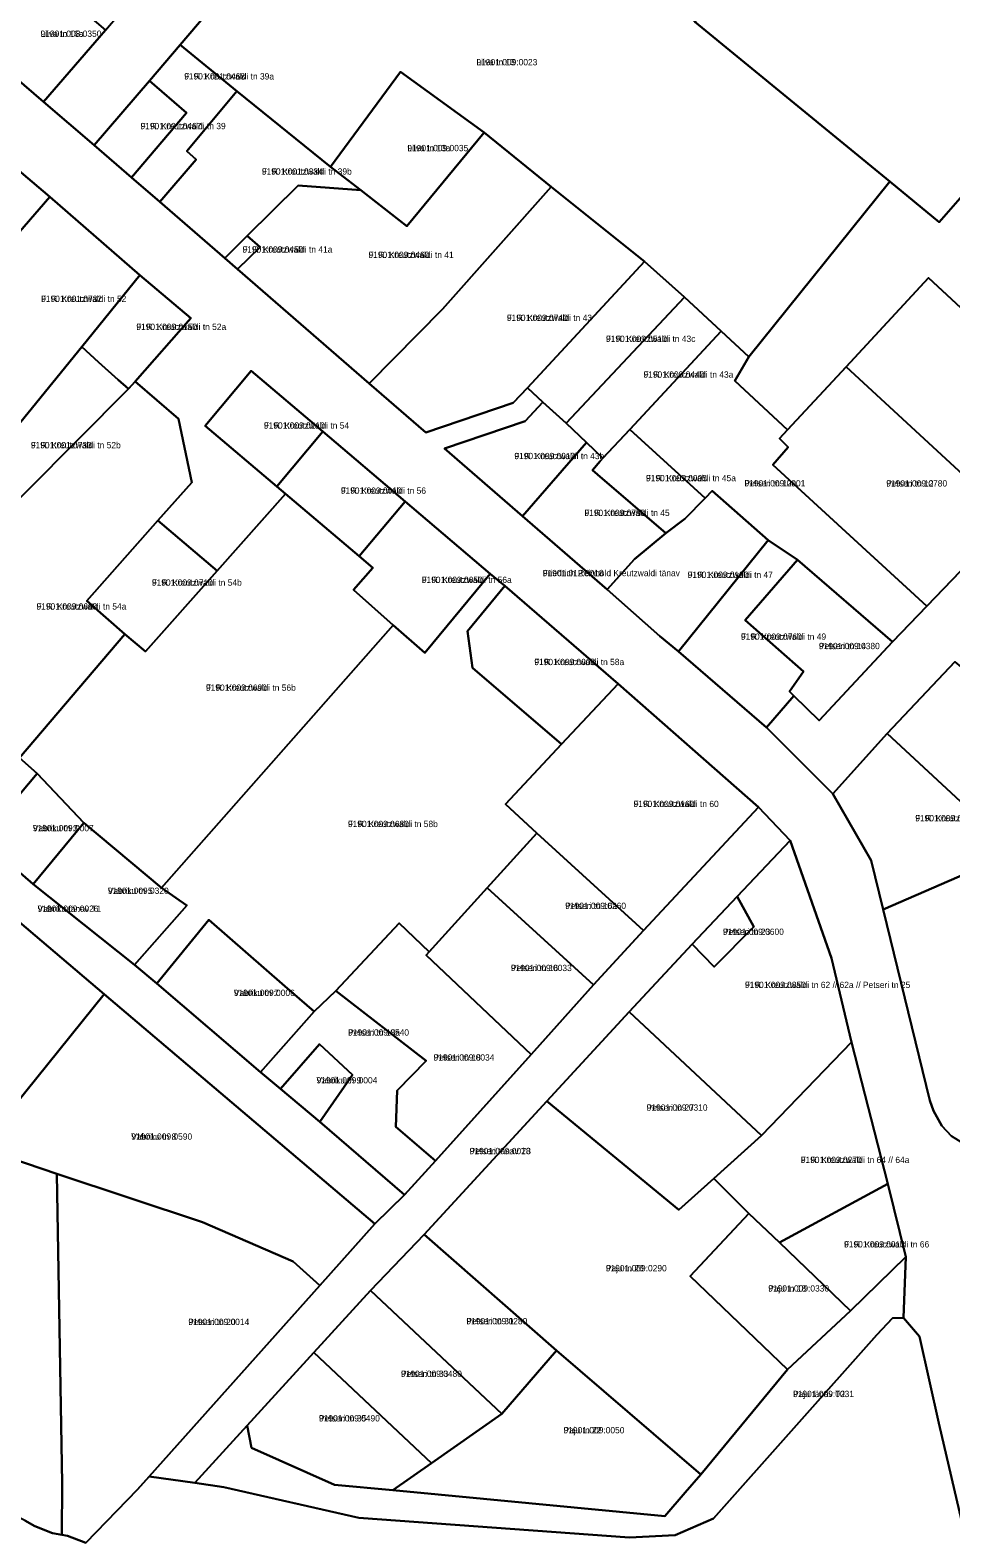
# Model space of a CAD drawing. Extents: x 675810 to 681273, y 6411190 to 6417565.
# Drawn here: x 678044.7 to 678264, y 6414897.2 to 6415256.1 of the extents above; entities that cross this region are included whole.
import ezdxf

# ---------------------------------------------------------------- set-up
doc = ezdxf.new("R2010")
doc.units = 0
for name, color, linetype in [('L_AADRESS', 7, 'Continuous'), ('PIIR', 7, 'Continuous'), ('TUNNUS', 7, 'Continuous')]:
    doc.layers.add(name, color=color, linetype=linetype)

msp = doc.modelspace()

# ---------------------------------------------------------------- linework, layer by layer
at = {"layer": 'PIIR'}
for points in [[(678198.81, 6415413.28), (678208.34, 6415402.14), (678200.49, 6415393.13), (678164.36, 6415350.68), (678161.07, 6415346.92), (678138.62, 6415320.63), (678158.43, 6415303.7), (678172.98, 6415291.47), (678169.9, 6415287.94), (678135.46, 6415317.19), (678080.44, 6415252.61), (678073.13, 6415244.08), (678060, 6415228.7), (678047.94, 6415239.03), (678062.66, 6415256.13), (678076.36, 6415272.05), (678099.99, 6415298.95), (678104.07, 6415303.65), (678126.77, 6415330.16), (678145.87, 6415352.47), (678149.44, 6415356.72), (678166.7, 6415375.98)], [(678286, 6415295.42), (678307.89, 6415320.24), (678311.89, 6415316.79), (678281.19, 6415282.24), (678297.38, 6415268.09), (678305.48, 6415261.06), (678291.98, 6415245.77), (678267.33, 6415217.4), (678261.23, 6415210.39), (678249.44, 6415220.06), (678203, 6415258.09), (678225.15, 6415284.07), (678228.71, 6415288.25), (678248, 6415310.9), (678261.57, 6415299.25), (678269.93, 6415309.22), (678270.63, 6415310.04)], [(678135.46, 6415317.19), (678169.9, 6415287.94), (678179.14, 6415279.62), (678203, 6415258.09), (678249.44, 6415220.06), (678215.92, 6415178.31), (678209.26, 6415184.48), (678200.6, 6415192.59), (678191.04, 6415201.02), (678168.78, 6415218.8), (678152.86, 6415231.73), (678132.93, 6415246.21), (678116.26, 6415223.58), (678093.94, 6415241.63), (678080.44, 6415252.61)], [(678046.56, 6415269.92), (678062.66, 6415256.13), (678047.94, 6415239.03), (678031.73, 6415252.94)], [(678081.99, 6415236.4), (678073.13, 6415244.08), (678080.44, 6415252.61), (678093.94, 6415241.63), (678082.01, 6415227.29), (678084.27, 6415225.36), (678075.6, 6415215.22), (678068.87, 6415221.01)], [(678132.93, 6415246.21), (678152.86, 6415231.73), (678134.44, 6415209.42), (678123.44, 6415218.03), (678116.26, 6415223.58)], [(678068.87, 6415221.01), (678060, 6415228.7), (678073.13, 6415244.08), (678081.99, 6415236.4)], [(678093.94, 6415241.63), (678116.26, 6415223.58), (678123.44, 6415218.03), (678108.53, 6415219.15), (678096.44, 6415207.12), (678091.12, 6415201.82), (678075.6, 6415215.22), (678084.27, 6415225.36), (678082.01, 6415227.29)], [(678094.14, 6415199.21), (678099.47, 6415204.49), (678096.44, 6415207.12), (678108.53, 6415219.15), (678123.44, 6415218.03), (678134.44, 6415209.42), (678152.86, 6415231.73), (678168.78, 6415218.8), (678142.93, 6415189.67), (678125.47, 6415172.03)], [(678037.29, 6415226.68), (678049.41, 6415216.4), (678023.87, 6415186.98), (677999.36, 6415158.83), (677982.03, 6415139.05), (677965.99, 6415120.49), (677959.89, 6415113.46), (677928.58, 6415077.34), (677882.86, 6415023.65), (677872.66, 6415034.51), (677904.65, 6415072.43), (677930.93, 6415102.56), (677951.46, 6415126.08), (677968.44, 6415145.74), (677980.8, 6415159.74), (678004.47, 6415187.8), (678013.63, 6415198.64)], [(678023.87, 6415186.98), (678049.41, 6415216.4), (678070.82, 6415197.78), (678057.06, 6415180.69), (678037.28, 6415156.5), (678030.6, 6415162.51), (678039.09, 6415173.99)], [(678142.93, 6415189.67), (678168.78, 6415218.8), (678191.04, 6415201.02), (678163.14, 6415170.98), (678159.79, 6415167.37), (678138.99, 6415160.32), (678125.47, 6415172.03)], [(678091.12, 6415201.82), (678096.44, 6415207.12), (678099.47, 6415204.49), (678094.14, 6415199.21)], [(678200.6, 6415192.59), (678172.35, 6415162.53), (678166.81, 6415167.58), (678163.14, 6415170.98), (678191.04, 6415201.02)], [(678082.96, 6415187.53), (678069.76, 6415172.45), (678068.17, 6415170.73), (678065.72, 6415172.89), (678061.01, 6415177.11), (678057.06, 6415180.69), (678070.82, 6415197.78)], [(678239.06, 6415175.98), (678258.66, 6415197.14), (678298.17, 6415160.58), (678278.26, 6415139.8)], [(678209.26, 6415184.48), (678187.54, 6415161.07), (678181.12, 6415154.2), (678177.19, 6415157.93), (678172.35, 6415162.53), (678200.6, 6415192.59)], [(678187.54, 6415161.07), (678209.26, 6415184.48), (678215.92, 6415178.31), (678212.58, 6415172.65), (678225.11, 6415161), (678223.16, 6415158.94), (678225.29, 6415156.87), (678221.64, 6415152.67), (678258.25, 6415118.98), (678250.12, 6415110.52), (678227.47, 6415130.05), (678220.53, 6415134.69), (678207.16, 6415146.42), (678205.48, 6415144.72)], [(678037.28, 6415156.5), (678057.06, 6415180.69), (678061.01, 6415177.11), (678065.72, 6415172.89), (678068.17, 6415170.73), (678031.79, 6415134.21), (678027.72, 6415137.35), (678021.6, 6415141.8), (678027.17, 6415148.45), (678022.82, 6415152.09), (678030.6, 6415162.51)], [(678097.33, 6415175.04), (678114.4, 6415160.6), (678103.51, 6415147.49), (678086.43, 6415161.9)], [(678225.11, 6415161), (678239.06, 6415175.98), (678278.26, 6415139.8), (678258.25, 6415118.98), (678221.64, 6415152.67), (678225.29, 6415156.87), (678223.16, 6415158.94)], [(678069.76, 6415172.45), (678080.05, 6415163.56), (678083.23, 6415148.47), (678075.16, 6415139.39), (678058.19, 6415120.25), (678067.3, 6415112.34), (678042.15, 6415082.88), (678029.02, 6415094.42), (678027.51, 6415095.75), (678015.11, 6415107.3), (678017.12, 6415109.61), (678009.23, 6415115.87), (678027.72, 6415137.35), (678031.79, 6415134.21), (678068.17, 6415170.73)], [(678166.81, 6415167.58), (678172.35, 6415162.53), (678177.19, 6415157.93), (678162.01, 6415140.39), (678143.38, 6415156.52), (678162.6, 6415163.04)], [(678134.02, 6415143.91), (678123.07, 6415130.89), (678105.57, 6415145.74), (678103.51, 6415147.49), (678114.4, 6415160.6)], [(678181.12, 6415154.2), (678187.54, 6415161.07), (678205.48, 6415144.72), (678200.62, 6415139.8), (678196.14, 6415136.39), (678179.84, 6415150.34), (678178.62, 6415151.38), (678180.48, 6415153.48)], [(678162.01, 6415140.39), (678177.19, 6415157.93), (678181.12, 6415154.2), (678180.48, 6415153.48), (678178.62, 6415151.38), (678179.84, 6415150.34), (678196.14, 6415136.39), (678188.64, 6415130.16), (678182.12, 6415122.99)], [(678131.21, 6415114.51), (678076.01, 6415051.96), (678057.54, 6415067.4), (678046.39, 6415079.16), (678042.15, 6415082.88), (678067.3, 6415112.34), (678072.16, 6415108.18), (678089.26, 6415127.4), (678105.57, 6415145.74), (678123.07, 6415130.89), (678126.3, 6415128.15), (678121.7, 6415122.92)], [(678191.23, 6415114.92), (678182.12, 6415122.99), (678188.64, 6415130.16), (678196.14, 6415136.39), (678200.62, 6415139.8), (678205.48, 6415144.72), (678207.16, 6415146.42), (678220.53, 6415134.69), (678199.12, 6415108.22), (678194.71, 6415111.83)], [(678123.07, 6415130.89), (678134.02, 6415143.91), (678154.29, 6415126.67), (678138.7, 6415107.87), (678131.21, 6415114.51), (678121.7, 6415122.92), (678126.3, 6415128.15)], [(678058.19, 6415120.25), (678075.16, 6415139.39), (678089.26, 6415127.4), (678072.16, 6415108.18), (678067.3, 6415112.34)], [(678227.47, 6415130.05), (678215.02, 6415115.64), (678228.89, 6415103.41), (678225.56, 6415098.67), (678226.61, 6415097.65), (678220.09, 6415090.11), (678199.12, 6415108.22), (678220.53, 6415134.69)], [(678250.12, 6415110.52), (678232.67, 6415091.77), (678226.61, 6415097.65), (678225.56, 6415098.67), (678228.89, 6415103.41), (678215.02, 6415115.64), (678227.47, 6415130.05)], [(678154.29, 6415126.67), (678157.77, 6415123.8), (678148.86, 6415113.06), (678150.07, 6415104.28), (678171.27, 6415086.11), (678157.92, 6415071.83), (678165.37, 6415064.97), (678153.59, 6415051.93), (678139.79, 6415036.69), (678132.61, 6415043.56), (678117.49, 6415027.42), (678112.38, 6415022.48), (678105.35, 6415028.57), (678087.24, 6415044.33), (678074.92, 6415029.17), (678069.54, 6415033.61), (678082.02, 6415047.77), (678076.01, 6415051.96), (678131.21, 6415114.51), (678138.7, 6415107.87)], [(678157.77, 6415123.8), (678184.74, 6415100.52), (678171.27, 6415086.11), (678150.07, 6415104.28), (678148.86, 6415113.06)], [(677965.99, 6415120.49), (677992.1, 6415097.75), (677992.48, 6415098.2), (678014.15, 6415079.56), (678033.17, 6415063.43), (678045.46, 6415052.81), (678069.54, 6415033.61), (678074.92, 6415029.17), (678099.61, 6415008.07), (678104.32, 6415004.09), (678113.73, 6414996.23), (678133.86, 6414978.84), (678126.85, 6414971.96), (678062.35, 6415026.65), (678027.28, 6415056.39), (678007.87, 6415072.59), (677988.71, 6415088.64), (677959.89, 6415113.46)], [(678248.8, 6415088.71), (678264.97, 6415105.73), (678272.33, 6415099.55), (678285.52, 6415089.51), (678290.53, 6415094.9), (678303.55, 6415082.79), (678309.26, 6415088.81), (678341.61, 6415057.78), (678339.56, 6415055.48), (678325.67, 6415068.43), (678310.56, 6415057.36), (678296.44, 6415043.18), (678279.3, 6415060.41)], [(678190.78, 6415041.82), (678165.37, 6415064.97), (678157.92, 6415071.83), (678171.27, 6415086.11), (678184.74, 6415100.52), (678218.21, 6415071.17)], [(678014.15, 6415079.56), (678027.51, 6415095.75), (678029.02, 6415094.42), (678042.15, 6415082.88), (678046.39, 6415079.16), (678033.17, 6415063.43)], [(678248.8, 6415088.71), (678279.3, 6415060.41), (678247.9, 6415046.82), (678245.04, 6415058.45), (678235.88, 6415074.34)], [(678046.39, 6415079.16), (678057.54, 6415067.4), (678045.46, 6415052.81), (678033.17, 6415063.43)], [(677981.13, 6415021.08), (677957.18, 6415041.12), (677955.51, 6415049.35), (677974.77, 6415072.44), (677994, 6415056.18), (678013.38, 6415040.14), (678027.28, 6415056.39), (678062.35, 6415026.65), (678032.85, 6414990.08), (678010.48, 6414995.29)], [(678218.21, 6415071.17), (678225.75, 6415063.23), (678213.1, 6415049.84), (678202.41, 6415038.55), (678187.39, 6415022.45), (678167.77, 6415001.12), (678138.59, 6414969.4), (678125.77, 6414956.06), (678112.27, 6414941.3), (678096.38, 6414923.92), (678083.91, 6414910.27), (678073.04, 6414911.8), (678113.69, 6414957.3), (678126.85, 6414971.96), (678133.86, 6414978.84), (678141.3, 6414986.92), (678164.08, 6415012.3), (678164.78, 6415013.09), (678178.91, 6415028.87), (678190.78, 6415041.82)], [(678082.02, 6415047.77), (678069.54, 6415033.61), (678045.46, 6415052.81), (678057.54, 6415067.4), (678076.01, 6415051.96)], [(678178.91, 6415028.87), (678153.59, 6415051.93), (678165.37, 6415064.97), (678190.78, 6415041.82)], [(678235.58, 6415035.17), (678240.37, 6415015.24), (678218.94, 6414992.95), (678187.39, 6415022.45), (678202.41, 6415038.55), (678207.65, 6415033.1), (678217.05, 6415042.63), (678213.1, 6415049.84), (678225.75, 6415063.23)], [(678279.3, 6415060.41), (678296.44, 6415043.18), (678289.38, 6415035.97), (678306.11, 6415020.2), (678280.79, 6414993.66), (678278.26, 6414991.56), (678276.16, 6414990.4), (678272.93, 6414989.72), (678268.13, 6414990.4), (678264.12, 6414992.85), (678261.88, 6414995.29), (678259.87, 6414998.84), (678259.01, 6415001.3), (678247.9, 6415046.82)], [(678153.59, 6415051.93), (678178.91, 6415028.87), (678164.78, 6415013.09), (678164.08, 6415012.3), (678139.04, 6415035.93), (678139.79, 6415036.69)], [(678217.05, 6415042.63), (678207.65, 6415033.1), (678202.41, 6415038.55), (678213.1, 6415049.84)], [(678087.24, 6415044.33), (678105.35, 6415028.57), (678112.38, 6415022.48), (678099.61, 6415008.07), (678074.92, 6415029.17)], [(678132.61, 6415043.56), (678139.79, 6415036.69), (678139.04, 6415035.93), (678164.08, 6415012.3), (678141.3, 6414986.92), (678131.8, 6414995.08), (678132.14, 6415003.66), (678139.02, 6415010.76), (678117.49, 6415027.42)], [(678032.85, 6414990.08), (678062.35, 6415026.65), (678126.85, 6414971.96), (678113.69, 6414957.3), (678107.35, 6414962.97), (678085.75, 6414972.33), (678051.11, 6414983.88)], [(678133.86, 6414978.84), (678113.73, 6414996.23), (678121.49, 6415007.45), (678113.65, 6415014.69), (678104.32, 6415004.09), (678099.61, 6415008.07), (678112.38, 6415022.48), (678117.49, 6415027.42), (678139.02, 6415010.76), (678132.14, 6415003.66), (678131.8, 6414995.08), (678141.3, 6414986.92)], [(678199.23, 6414975.31), (678167.77, 6415001.12), (678187.39, 6415022.45), (678218.94, 6414992.95), (678207.55, 6414982.74)], [(678215.89, 6414974.39), (678207.55, 6414982.74), (678218.94, 6414992.95), (678240.37, 6415015.24), (678248.97, 6414981.45), (678223.22, 6414967.48)], [(678113.65, 6415014.69), (678121.49, 6415007.45), (678113.73, 6414996.23), (678104.32, 6415004.09)], [(678170.07, 6414941.78), (678138.59, 6414969.4), (678167.77, 6415001.12), (678199.23, 6414975.31), (678207.55, 6414982.74), (678215.89, 6414974.39), (678201.88, 6414959.51), (678225.07, 6414937.29), (678204.47, 6414912.3)], [(677992.45, 6414906.2), (677988.65, 6414906.85), (677984.94, 6414907.96), (677983.4, 6414909.02), (677983.03, 6414910.96), (677983.04, 6414911.49), (677991.14, 6414923.6), (678032.85, 6414990.08), (678051.11, 6414983.88), (678052.36, 6414910.12), (678052.24, 6414897.91), (678050.05, 6414898.29), (678045.82, 6414899.97), (678043.42, 6414901.31), (678040.91, 6414902.63), (678037.2, 6414904.74), (678031.34, 6414905.74), (678019.61, 6414908.42), (678016.38, 6414909.14), (678009.58, 6414909.37), (678002.82, 6414909.05), (677997.85, 6414907.65), (677994.08, 6414906.17)], [(678052.36, 6414910.12), (678051.11, 6414983.88), (678085.75, 6414972.33), (678107.35, 6414962.97), (678113.69, 6414957.3), (678073.04, 6414911.8), (678070.27, 6414908.75), (678057.96, 6414895.98), (678053.65, 6414897.68), (678052.24, 6414897.91)], [(678223.22, 6414967.48), (678248.97, 6414981.45), (678253.26, 6414964.14), (678240.09, 6414951.21)], [(678201.88, 6414959.51), (678215.89, 6414974.39), (678223.22, 6414967.48), (678240.09, 6414951.21), (678225.07, 6414937.29)], [(678125.77, 6414956.06), (678138.59, 6414969.4), (678170.07, 6414941.78), (678157.08, 6414926.7)], [(678253.26, 6414964.14), (678252.73, 6414949.61), (678250.14, 6414949.54), (678246.38, 6414945.52), (678207.47, 6414901.85), (678198.38, 6414897.86), (678187.43, 6414897.28), (678123, 6414901.96), (678090.83, 6414909.3), (678083.91, 6414910.27), (678096.38, 6414923.92), (678097.41, 6414918.63), (678117.19, 6414909.85), (678131.07, 6414908.52), (678195.89, 6414902.37), (678200.76, 6414908), (678204.47, 6414912.3), (678225.07, 6414937.29), (678240.09, 6414951.21)], [(678112.27, 6414941.3), (678125.77, 6414956.06), (678157.08, 6414926.7), (678140.32, 6414914.98)], [(678096.38, 6414923.92), (678112.27, 6414941.3), (678140.32, 6414914.98), (678131.07, 6414908.52), (678117.19, 6414909.85), (678097.41, 6414918.63)], [(678200.76, 6414908), (678195.89, 6414902.37), (678131.07, 6414908.52), (678140.32, 6414914.98), (678157.08, 6414926.7), (678170.07, 6414941.78), (678204.47, 6414912.3)]]:
    msp.add_lwpolyline(points, close=True, dxfattribs=at)
for points in [[(678031.73, 6415252.94), (678047.94, 6415239.03), (678060, 6415228.7), (678068.87, 6415221.01), (678075.6, 6415215.22), (678091.12, 6415201.82), (678094.14, 6415199.21), (678125.47, 6415172.03), (678138.99, 6415160.32), (678159.79, 6415167.37), (678163.14, 6415170.98), (678166.81, 6415167.58), (678162.6, 6415163.04), (678143.38, 6415156.52), (678162.01, 6415140.39), (678182.12, 6415122.99), (678191.23, 6415114.92), (678194.71, 6415111.83), (678199.12, 6415108.22), (678220.09, 6415090.11), (678235.88, 6415074.34), (678245.04, 6415058.45), (678247.9, 6415046.82), (678259.01, 6415001.3), (678259.87, 6414998.84), (678261.88, 6414995.29), (678264.12, 6414992.85)], [(678331.34, 6414623.63), (678261.12, 6414924.5), (678256.56, 6414945.14), (678252.73, 6414949.61), (678253.26, 6414964.14), (678248.97, 6414981.45), (678240.37, 6415015.24), (678235.58, 6415035.17), (678225.75, 6415063.23), (678218.21, 6415071.17), (678184.74, 6415100.52), (678157.77, 6415123.8), (678154.29, 6415126.67), (678134.02, 6415143.91), (678114.4, 6415160.6), (678097.33, 6415175.04), (678086.43, 6415161.9), (678103.51, 6415147.49), (678105.57, 6415145.74), (678089.26, 6415127.4), (678075.16, 6415139.39), (678083.23, 6415148.47), (678080.05, 6415163.56), (678069.76, 6415172.45), (678082.96, 6415187.53), (678070.82, 6415197.78), (678049.41, 6415216.4), (678037.29, 6415226.68)], [(678298.17, 6415160.58), (678258.66, 6415197.14), (678239.06, 6415175.98), (678225.11, 6415161), (678212.58, 6415172.65), (678215.92, 6415178.31), (678249.44, 6415220.06), (678261.23, 6415210.39), (678267.33, 6415217.4)], [(678264.97, 6415105.73), (678248.8, 6415088.71), (678235.88, 6415074.34), (678220.09, 6415090.11), (678226.61, 6415097.65), (678232.67, 6415091.77), (678250.12, 6415110.52), (678258.25, 6415118.98), (678278.26, 6415139.8)], [(678057.96, 6414895.98), (678070.27, 6414908.75), (678073.04, 6414911.8), (678083.91, 6414910.27), (678090.83, 6414909.3), (678123, 6414901.96), (678187.43, 6414897.28), (678198.38, 6414897.86), (678207.47, 6414901.85), (678246.38, 6414945.52), (678250.14, 6414949.54), (678252.73, 6414949.61), (678256.56, 6414945.14), (678261.12, 6414924.5), (678331.34, 6414623.63)], [(678043.42, 6414901.31), (678045.82, 6414899.97), (678050.05, 6414898.29), (678052.24, 6414897.91), (678053.65, 6414897.68), (678057.96, 6414895.98)]]:
    msp.add_lwpolyline(points, dxfattribs=at)

# ---------------------------------------------------------------- texts
at = {"layer": 'L_AADRESS'}
for s, p in [('Liiva tn 16a', (678047.19, 6415254.52)), ('Liiva tn 13', (678151.02, 6415247.75)), ('F. R. Kreutzwaldi tn 39a', (678081.4, 6415244.37)), ('F. R. Kreutzwaldi tn 39', (678071, 6415232.54)), ('Liiva tn 13a', (678134.56, 6415227.3)), ('F. R. Kreutzwaldi tn 39b', (678099.91, 6415221.73)), ('F. R. Kreutzwaldi tn 41a', (678095.3, 6415203.17)), ('F. R. Kreutzwaldi tn 41', (678125.3, 6415201.88)), ('F. R. Kreutzwaldi tn 52', (678047.34, 6415191.42)), ('F. R. Kreutzwaldi tn 43', (678158.25, 6415186.89)), ('F. R. Kreutzwaldi tn 52a', (678070.01, 6415184.75)), ('F. R. Kreutzwaldi tn 43c', (678181.87, 6415181.9)), ('F. R. Kreutzwaldi tn 43a', (678190.8, 6415173.38)), ('F. R. Kreutzwaldi tn 54', (678100.4, 6415161.26)), ('F. R. Kreutzwaldi tn 52b', (678044.89, 6415156.58)), ('F. R. Kreutzwaldi tn 43b', (678160.04, 6415153.99)), ('F. R. Kreutzwaldi tn 45a', (678191.4, 6415148.73)), ('Petseri tn 12a', (678214.84, 6415147.5)), ('Petseri tn 12', (678248.61, 6415147.48)), ('F. R. Kreutzwaldi tn 56', (678118.71, 6415145.75)), ('F. R. Kreutzwaldi tn 45', (678176.73, 6415140.46)), ('Friedrich Reinhold Kreutzwaldi tänav', (678166.8, 6415126.13)), ('F. R. Kreutzwaldi tn 47', (678201.32, 6415125.73)), ('F. R. Kreutzwaldi tn 54b', (678073.72, 6415123.86)), ('F. R. Kreutzwaldi tn 56a', (678138, 6415124.51)), ('F. R. Kreutzwaldi tn 54a', (678046.23, 6415118.18)), ('F. R. Kreutzwaldi tn 49', (678214, 6415110.99)), ('Petseri tn 14', (678232.57, 6415108.76)), ('F. R. Kreutzwaldi tn 58a', (678164.79, 6415104.96)), ('F. R. Kreutzwaldi tn 56b', (678086.59, 6415098.85)), ('F. R. Kreutzwaldi tn 60', (678188.42, 6415071.17)), ('F. R. Kreutzwaldi tn 51', (678255.52, 6415067.77)), ('Vabriku tn 3', (678045.36, 6415065.41)), ('F. R. Kreutzwaldi tn 58b', (678120.41, 6415066.4)), ('Vabriku tn 5', (678063.22, 6415050.5)), ('Vabriku tänav T1', (678046.49, 6415046.23)), ('Petseri tn 16a', (678172.14, 6415046.92)), ('Petseri tn 23', (678209.73, 6415040.74)), ('Petseri tn 16', (678159.21, 6415032.12)), ('F. R. Kreutzwaldi tn 62 // 62a // Petseri tn 25', (678214.97, 6415028.09)), ('Vabriku tn 7', (678093.24, 6415026.2)), ('Petseri tn 18a', (678120.45, 6415016.77)), ('Petseri tn 18', (678140.79, 6415010.82)), ('Vabriku tn 9', (678112.91, 6415005.38)), ('Petseri tn 27', (678191.55, 6414998.88)), ('Vabriku tn 8', (678068.81, 6414991.98)), ('Petseri tänav T3', (678149.39, 6414988.54)), ('F. R. Kreutzwaldi tn 64 // 64a', (678228.26, 6414986.43)), ('F. R. Kreutzwaldi tn 66', (678238.56, 6414966.33)), ('Paju tn 20', (678181.83, 6414960.64)), ('Paju tn 18', (678220.5, 6414955.84)), ('Petseri tn 20', (678082.4, 6414947.86)), ('Petseri tn 31', (678148.62, 6414948.05)), ('Petseri tn 33', (678133.05, 6414935.52)), ('Paju tänav T2', (678226.42, 6414930.71)), ('Petseri tn 35', (678113.51, 6414924.91)), ('Paju tn 22', (678171.76, 6414922.08))]:
    msp.add_text(s, height=1.5, dxfattribs=at).set_placement(p)
at = {"layer": 'TUNNUS'}
for s, p in [('91901:008:0350', (678047.19, 6415254.52)), ('91901:009:0023', (678151.02, 6415247.75)), ('91901:001:0468', (678081.4, 6415244.37)), ('91901:001:0467', (678071, 6415232.54)), ('91901:009:0035', (678134.56, 6415227.3)), ('91901:001:0334', (678099.91, 6415221.73)), ('91901:009:0450', (678095.3, 6415203.17)), ('91901:009:0460', (678125.3, 6415201.88)), ('91901:001:0732', (678047.34, 6415191.42)), ('91901:009:0740', (678158.25, 6415186.89)), ('91901:009:0150', (678070.01, 6415184.75)), ('91901:009:0510', (678181.87, 6415181.9)), ('91901:009:0440', (678190.8, 6415173.38)), ('91901:009:0210', (678100.4, 6415161.26)), ('91901:001:0733', (678044.89, 6415156.58)), ('91901:009:0012', (678160.04, 6415153.99)), ('91901:009:0005', (678191.4, 6415148.73)), ('91901:009:0001', (678214.84, 6415147.5)), ('91901:009:0780', (678248.61, 6415147.48)), ('91901:009:0010', (678118.71, 6415145.75)), ('91901:009:0750', (678176.73, 6415140.46)), ('91901:012:0018', (678166.8, 6415126.13)), ('91901:009:0190', (678201.32, 6415125.73)), ('91901:009:0710', (678073.72, 6415123.86)), ('91901:009:0650', (678138, 6415124.51)), ('91901:009:0660', (678046.23, 6415118.18)), ('91901:009:0760', (678214, 6415110.99)), ('91901:009:0380', (678232.57, 6415108.76)), ('91901:009:0008', (678164.79, 6415104.96)), ('91901:009:0690', (678086.59, 6415098.85)), ('91901:009:0160', (678188.42, 6415071.17)), ('91901:009:0020', (678255.52, 6415067.77)), ('91901:009:0007', (678045.36, 6415065.41)), ('91901:009:0680', (678120.41, 6415066.4)), ('91901:009:0320', (678063.22, 6415050.5)), ('91901:009:0026', (678046.49, 6415046.23)), ('91901:009:0260', (678172.14, 6415046.92)), ('91901:009:0600', (678209.73, 6415040.74)), ('91901:009:0033', (678159.21, 6415032.12)), ('91901:009:0350', (678214.97, 6415028.09)), ('91901:009:0006', (678093.24, 6415026.2)), ('91901:009:0540', (678120.45, 6415016.77)), ('91901:009:0034', (678140.79, 6415010.82)), ('91901:009:0004', (678112.91, 6415005.38)), ('91901:009:0310', (678191.55, 6414998.88)), ('91901:009:0590', (678068.81, 6414991.98)), ('91901:009:0028', (678149.39, 6414988.54)), ('91901:009:0270', (678228.26, 6414986.43)), ('91901:009:0013', (678238.56, 6414966.33)), ('91901:009:0290', (678181.83, 6414960.64)), ('91901:009:0330', (678220.5, 6414955.84)), ('91901:009:0014', (678082.4, 6414947.86)), ('91901:009:0280', (678148.62, 6414948.05)), ('91901:009:0480', (678133.05, 6414935.52)), ('91901:009:0031', (678226.42, 6414930.71)), ('91901:009:0490', (678113.51, 6414924.91)), ('91901:009:0050', (678171.76, 6414922.08))]:
    msp.add_text(s, height=1.5, dxfattribs=at).set_placement(p)

doc.saveas('drawing.dxf')
